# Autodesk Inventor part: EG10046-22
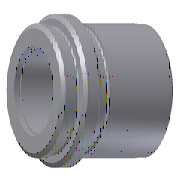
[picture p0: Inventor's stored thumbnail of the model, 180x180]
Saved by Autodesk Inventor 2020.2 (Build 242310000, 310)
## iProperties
Manager: www.cadconsulting.pl
Company: Fabian Stasiak CAD Consulting
Created: 2014-02
Part Number: EG10046-22
Material: DIN 1.7131
Description: Leader Pin Bushings
Document SubType Name: Modeling
Designer: F.Stasiak
Standard Revision: 1
Manufacturer: DME
Language: pl-PL
Size Designation: 46-22
Categories: <MemberInstance><Categories><Category DisplayName="Forma wtryskowa" InternalName="349578f2-f4d4-4954-8c09-8e99297a61c0" Mnemonic="MOLD"><Category DisplayName="K
Density: 7.85 g/cm^3
Appearance: Domyślna
Catalog Web Link: www.expertbooks.pl
IsCustomPart: 0
Author: F.Stasiak
Subject: Zbiór ćwiczeń. Autodesk Inventor 2020. Kurs Professional
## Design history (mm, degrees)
sketch "Sketch1"
  geometry: L1 (0, -16.8)-(0, 9.8) reference; L2 (0, 15)-(15, 15); L3 (15, 15)-(15, 7); L4 (15, 7)-(14.5, 7); L5 (14.5, 7)-(14.5, 6); L6 (14.5, 6)-(17.5, 6); L7 (17.5, 6)-(17.5, 0); L8 (17.5, 0)-(14.5, 0); L9 (14.5, 0)-(14.5, -1); L10 (14.5, -1)-(15, -1); L11 (15, -1)-(15, -39); L12 (15, -39)-(14.95, -39); L13 (14.95, -39)-(14.95, -40); L14 (14.95, -40)-(0, -40); L15 (0, 15)-(0, -40); 1 further point
  constraints: 28 end point, 7 parallel, 5 perpendicular, 2 collinear, 2 equal length, 2 point on line, 1 horizontal alignment
  dimensions: "d0" = 30 diameter of L11 L1 (= D); "d2" = 1 distance between parallel lines of L14 L12; "d27" = 29.9 diameter of L13 L1 (= D_Guide); "d4" = 35 diameter of L7 L1 (= D2); "d5" = 30 diameter of L3 L1 (= D1); "d6" = 6 distance between parallel lines of L8 L6 (= H_); "d7" = 46 distance between parallel lines of L14 L6 (= L); "d8" = 9 distance between parallel lines of L6 L2 (= L1); "d9" = 1 distance between parallel lines of L10 L8; "d10" = 0.5 distance between parallel lines of L11 L9
revolve "Revolution1" sketch "Sketch1" stored, may be unused: angle "d11" = 90 deg
sketch "Sketch2"
  geometry: L1 (-14.95, -40)-(14.95, -40) reference; L2 (11, -40)-(11, 6); L3 (11, 6)-(11, 6); L4 (11, 6)-(11, 61); L5 (0, -40)-(0, 61); L6 (0, 61)-(11, 61); L7 (11, -40)-(0, -40)
  constraints: 12 end point, 3 perpendicular, 2 collinear, 1 midpoint, 1 parallel, 1 point on line
  dimensions: "d12" = 22 diameter of L2 L5 (= d_); "d13" = 46 distance of L2.start L2.end (= l_); "d14" = 55 distance of L3.end L4.end (= L + L1); "d15" = 22 diameter of L4 L5 (= d3)
revolve "Revolution2" sketch "Sketch2" stored, may be unused: angle "d16" = 90 deg
chamfer "Chamfer1" distance "d17" = 0.5; stored, may be unused: second distance "d18" = 2, angle "d19" = 45 deg
fillet "Fillet1" dims "d20" = 0.3
fillet "Fillet2" dims "d21" = 0.8
body "Solid1"
other parameters: "d_" = 22 [user parameter; used in 1 equation term], "L" = 46 [user parameter; used in 2 equation terms], "D" = 30 [user parameter; used in 1 equation term], "D1" = 30 [user parameter; used in 1 equation term], "D2" = 35 [user parameter; used in 1 equation term], "H_" = 6 [user parameter; used in 1 equation term], "L1" = 9 [user parameter; used in 2 equation terms], "l_" = 46 [user parameter; used in 1 equation term], "d3" = 22 [user parameter; used in 1 equation term], "D_Guide" = 29.9 [user parameter; used in 1 equation term], "d22" = 0, "d23" = 0, "d24" = 0, "d25" = 0, "d26" = 0
